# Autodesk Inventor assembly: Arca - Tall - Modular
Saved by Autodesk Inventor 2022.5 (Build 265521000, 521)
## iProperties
Created: 2025-01
Part Number: Arca - Tall - Modular
Document SubType Name: Assembly
Designer: AdminForWorker
Title: Arca - Tall - Modular v10
Author: AdminForWorker
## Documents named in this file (4)
- c:\worker\convert-fusion-r06-cosv3\tmp\job-1\11\temp\files\bf84bd78-2eff-46e5-910a-b499271509d8\c9ebfa3b-98bb-4145-84a8-d1364ad16070.iam
- c:\worker\convert-fusion-r06-cosv3\tmp\job-1\11\temp\files\bf84bd78-2eff-46e5-910a-b499271509d8\Modular - Placebo - Bayonet Connector v4.ipt
- c:\worker\convert-fusion-r06-cosv3\tmp\job-1\11\temp\files\bf84bd78-2eff-46e5-910a-b499271509d8\Arca Tall V2 - Modular.ipt
- c:\worker\convert-fusion-r06-cosv3\tmp\job-1\11\temp\files\bf84bd78-2eff-46e5-910a-b499271509d8\Modular - Placedo - Cord Set v4.ipt
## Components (3 placed, 3 different names)
1. Modular - Placebo - Bayonet Connector v4:1
2. Arca Tall V2 - Modular:1
3. Modular - Placedo - Cord Set v4:1
